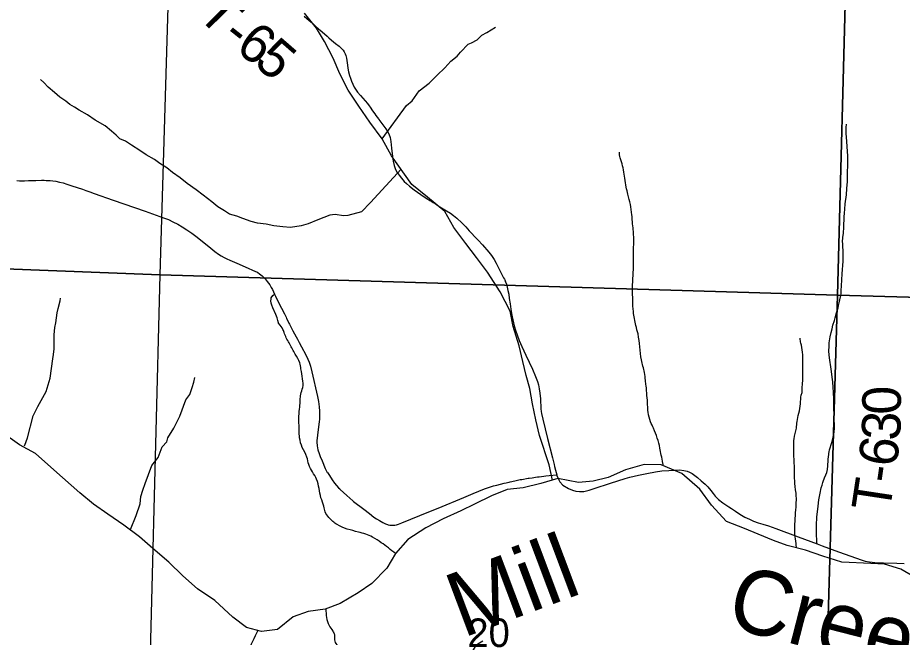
# Model space of a CAD drawing. Extents: x 6.3 to 40.3, y 9 to 31.
# Drawn here: x 9.108 to 10.406, y 26.729 to 27.639 of the extents above; entities that cross this region are included whole.
import ezdxf

# ---------------------------------------------------------------- set-up
doc = ezdxf.new("R2010")
doc.units = 0
for name, color, linetype in [('GM_X_Corporation', 7, 'Continuous'), ('GM_X_Minor_River', 7, 'Continuous'), ('GM_X_Minor_River_Text', 7, 'Continuous'), ('GM_X_Section', 7, 'Continuous'), ('GM_X_Section_Text', 7, 'Continuous'), ('GM_X_Township_Road', 7, 'Continuous'), ('GM_X_Township_Road_Text', 7, 'Continuous')]:
    doc.layers.add(name, color=color, linetype=linetype)

msp = doc.modelspace()

# ---------------------------------------------------------------- linework, layer by layer
at = {"layer": 'GM_X_Corporation'}
for points in [[(8.4446, 28.2864), (8.4446, 27.2958), (9.3175, 27.262), (9.3471, 28.2622)], [(8.4446, 27.2958), (8.4446, 26.2901), (9.2921, 26.2668), (9.3175, 27.262)]]:
    msp.add_lwpolyline(points, close=True, dxfattribs=at)
at = {"layer": 'GM_X_Minor_River'}
for points in [[(9.8928, 26.9603), (9.8883, 26.9826), (9.8739, 27.0256), (9.8686, 27.049), (9.8636, 27.0724), (9.8599, 27.0947), (9.8546, 27.114), (9.8493, 27.1347), (9.844, 27.1577), (9.8353, 27.1861), (9.8311, 27.2083), (9.8163, 27.237), (9.7978, 27.2657), (9.7815, 27.2872), (9.7656, 27.308), (9.7482, 27.3314), (9.7349, 27.3548), (9.7096, 27.3759), (9.6865, 27.3944), (9.657, 27.4367), (9.643, 27.4616), (9.6252, 27.4862), (9.6089, 27.5096), (9.5934, 27.533), (9.5809, 27.5568), (9.571, 27.5802), (9.5586, 27.6047), (9.5468, 27.624), (9.529, 27.6462)], [(9.6431, 27.4618), (9.643, 27.4616), (9.6789, 27.5103), (9.6872, 27.5172), (9.6973, 27.5321), (9.712, 27.5433), (9.724, 27.5552), (9.7349, 27.5656), (9.7439, 27.5755), (9.7533, 27.5829), (9.7578, 27.589), (9.7695, 27.6005), (9.774, 27.6025), (9.7823, 27.6071), (9.7891, 27.6136), (9.7966, 27.6175), (9.8095, 27.6256)], [(9.6709, 27.4168), (9.6257, 27.368), (9.6126, 27.3542), (9.5925, 27.3487), (9.5861, 27.3486), (9.5743, 27.3504), (9.5663, 27.3492), (9.5485, 27.3425), (9.5346, 27.3367), (9.5243, 27.3339), (9.5084, 27.3314), (9.4974, 27.3321), (9.4841, 27.3338), (9.473, 27.336), (9.4601, 27.3378), (9.4506, 27.3403), (9.4388, 27.3444), (9.4296, 27.3481), (9.419, 27.351), (9.4117, 27.3559), (9.4021, 27.3618), (9.3933, 27.3689), (9.3803, 27.3787), (9.37, 27.3865), (9.357, 27.3959), (9.3466, 27.4042), (9.3352, 27.412), (9.3271, 27.4191), (9.3168, 27.4251), (9.3088, 27.4311), (9.2969, 27.4382), (9.2873, 27.4445), (9.2751, 27.452), (9.2663, 27.458), (9.2583, 27.4617), (9.2525, 27.4669), (9.246, 27.4726), (9.2365, 27.4804), (9.2219, 27.489), (9.2108, 27.4969), (9.1986, 27.5036), (9.1914, 27.5081), (9.1849, 27.5122), (9.1791, 27.5167), (9.1699, 27.5227), (9.1623, 27.5298), (9.1527, 27.5373), (9.1465, 27.5441), (9.1419, 27.5489)], [(9.1179, 27.0109), (9.1188, 27.0117), (9.1225, 27.0223), (9.1309, 27.0547), (9.1379, 27.0685), (9.1498, 27.0902), (9.1557, 27.11), (9.1596, 27.1382), (9.161, 27.1447), (9.1617, 27.153), (9.1616, 27.1602), (9.1615, 27.1739), (9.1625, 27.1842), (9.164, 27.1914), (9.1661, 27.2059), (9.1675, 27.2123), (9.1705, 27.2234), (9.1708, 27.2276)], [(9.274, 26.888), (9.282, 26.9082), (9.2879, 26.9254), (9.289, 26.936), (9.2919, 26.9456), (9.2952, 26.9555), (9.3052, 26.9818), (9.3142, 26.9936), (9.3201, 27.0093), (9.3272, 27.0166), (9.3283, 27.0223), (9.3372, 27.0368), (9.3462, 27.0544), (9.355, 27.0784), (9.3606, 27.086), (9.3643, 27.0963), (9.3665, 27.1043), (9.3683, 27.1112)], [(9.5593, 26.7708), (9.5347, 26.7674), (9.5123, 26.7595), (9.4893, 26.741), (9.4662, 26.738), (9.4438, 26.7436), (9.4241, 26.7591), (9.3973, 26.7833), (9.3719, 26.8006), (9.3507, 26.8199), (9.3299, 26.8399), (9.3064, 26.8599), (9.2871, 26.8772), (9.264, 26.8942), (9.2405, 26.9101), (9.2193, 26.9252), (9.1996, 26.9414), (9.1614, 26.9754), (9.1345, 26.9995), (9.1111, 27.012), (9.0853, 27.0301)], [(10.4254, 26.8173), (10.4042, 26.8294), (10.38, 26.8366), (10.3603, 26.8377), (10.3176, 26.84), (10.2895, 26.8486), (10.2642, 26.8573), (10.2373, 26.8641), (10.2172, 26.8717), (10.1949, 26.8807), (10.1748, 26.8894), (10.1483, 26.8996), (10.1264, 26.9237), (10.109, 26.9471), (10.0828, 26.9698), (10.0526, 26.9826), (10.0276, 26.9834), (10.0003, 26.9754), (9.9749, 26.9641), (9.9526, 26.9588), (9.931, 26.9569), (9.9007, 26.9626), (9.8758, 26.9554), (9.85, 26.949), (9.8265, 26.9464), (9.8035, 26.9373), (9.7788, 26.9248), (9.7584, 26.915), (9.7327, 26.9033), (9.7069, 26.8901), (9.6808, 26.8731), (9.6626, 26.8527), (9.6498, 26.8312), (9.6278, 26.8086), (9.6077, 26.7946), (9.5816, 26.7791), (9.5593, 26.7708)]]:
    msp.add_lwpolyline(points, dxfattribs=at)
for points in [[(10.0554, 26.9824), (10.0551, 26.9849), (10.0527, 26.997), (10.0507, 27.0072), (10.0413, 27.0364), (10.037, 27.0458), (10.0334, 27.0599), (10.0326, 27.0709), (10.0304, 27.0986), (10.0295, 27.1069), (10.0279, 27.1183), (10.0235, 27.1368), (10.0185, 27.1751), (10.0154, 27.1873), (10.0117, 27.2077), (10.0108, 27.2237), (10.0112, 27.2609), (10.0118, 27.2712), (10.0117, 27.2825), (10.0119, 27.297), (10.0121, 27.3205), (10.0116, 27.3277), (10.0103, 27.3399), (10.0095, 27.3501), (10.0038, 27.3801), (10.0011, 27.3907), (9.999, 27.4036), (9.9942, 27.4278), (9.9923, 27.4335), (9.9914, 27.438), (9.9914, 27.4422)], [(9.6626, 26.8527), (9.6417, 26.8684), (9.6291, 26.8766), (9.6081, 26.884), (9.5769, 26.8951), (9.565, 26.9052), (9.5596, 26.9135), (9.5576, 26.9218), (9.5533, 26.9343), (9.5469, 26.9616), (9.5353, 26.9831), (9.5325, 26.9941), (9.5259, 27.0081), (9.5219, 27.0225), (9.521, 27.0437), (9.5209, 27.0543), (9.5222, 27.0676), (9.5229, 27.0779), (9.5235, 27.0863), (9.5265, 27.0962), (9.5263, 27.1091), (9.5239, 27.1235), (9.5223, 27.1326), (9.5153, 27.1454), (9.5076, 27.1598), (9.4998, 27.1753), (9.4975, 27.1817), (9.4917, 27.19)], [(10.2512, 26.8607), (10.2504, 26.8674), (10.2488, 26.8803), (10.2486, 26.8917), (10.2506, 26.9247), (10.2508, 26.9365), (10.2487, 26.9555), (10.2482, 26.971), (10.247, 27.0101), (10.2476, 27.0211), (10.2509, 27.0367), (10.2519, 27.0463), (10.2545, 27.0584), (10.257, 27.0725), (10.258, 27.085), (10.2594, 27.0904), (10.2594, 27.0965), (10.2601, 27.1025), (10.2603, 27.1177), (10.2605, 27.1303), (10.2583, 27.1584), (10.2568, 27.1648), (10.2563, 27.169)], [(9.5603, 26.7712), (9.5651, 26.7468), (9.5705, 26.7386), (9.5729, 26.7333), (9.573, 26.7257), (9.5765, 26.7185), (9.5822, 26.714), (9.5918, 26.7057), (9.601, 26.6975), (9.6079, 26.6919), (9.617, 26.6882), (9.6251, 26.6818), (9.6346, 26.6789), (9.6396, 26.6766), (9.651, 26.673), (9.6582, 26.6723), (9.6681, 26.6728), (9.6783, 26.674), (9.6897, 26.6757), (9.7034, 26.6769), (9.7079, 26.6778), (9.7166, 26.6801), (9.7242, 26.6836), (9.7329, 26.686), (9.7472, 26.693), (9.751, 26.6983), (9.7616, 26.7007), (9.7714, 26.7046), (9.7755, 26.7085), (9.7815, 26.718), (9.7909, 26.7242)], [(9.4604, 26.7394), (9.4448, 26.6757), (9.4487, 26.6647), (9.4522, 26.6553), (9.4565, 26.6439), (9.4646, 26.6357), (9.4692, 26.6327), (9.4776, 26.6221), (9.4837, 26.618), (9.493, 26.6082), (9.4979, 26.6045), (9.506, 26.5943), (9.511, 26.591), (9.5187, 26.5842), (9.5225, 26.5782), (9.5302, 26.571), (9.5409, 26.5617), (9.5474, 26.5553), (9.5494, 26.5511), (9.5571, 26.5425), (9.559, 26.5379), (9.5629, 26.533), (9.5736, 26.5218), (9.5863, 26.512), (9.5905, 26.5064), (9.5989, 26.5), (9.6066, 26.4929)]]:
    msp.add_spline(points, degree=3, dxfattribs=at)
at = {"layer": 'GM_X_Section'}
for points in [[(9.3471, 28.2622), (10.3378, 28.2352), (10.3113, 27.232), (9.3175, 27.262)], [(10.3378, 28.2352), (11.3334, 28.2025), (11.3031, 27.2038), (10.3113, 27.232)], [(9.3175, 27.262), (10.3113, 27.232), (10.2824, 26.2364), (9.2921, 26.2668)], [(10.3113, 27.232), (11.3031, 27.2038), (11.2666, 26.2073), (10.2824, 26.2364)]]:
    msp.add_lwpolyline(points, close=True, dxfattribs=at)
at = {"layer": 'GM_X_Township_Road'}
for points in [[(9.5288, 27.6416), (9.5358, 27.6354), (9.5401, 27.6319), (9.5451, 27.6272), (9.5497, 27.6231), (9.5521, 27.621), (9.5582, 27.6158), (9.5624, 27.6121), (9.5647, 27.61), (9.5689, 27.6064), (9.5746, 27.6016), (9.5799, 27.5974), (9.5831, 27.5945), (9.5856, 27.5918), (9.5874, 27.5893), (9.5888, 27.5865), (9.5898, 27.5837), (9.5906, 27.5801), (9.592, 27.5695), (9.5927, 27.5654), (9.5939, 27.56), (9.5953, 27.5547), (9.5964, 27.5506), (9.5983, 27.5464), (9.6021, 27.5376), (9.6039, 27.5344), (9.6067, 27.5303), (9.6111, 27.525), (9.6181, 27.5172), (9.6213, 27.5133), (9.6239, 27.5099), (9.6254, 27.5079), (9.6291, 27.5029), (9.6323, 27.4983), (9.634, 27.4958), (9.6357, 27.4933), (9.6376, 27.4908), (9.6382, 27.4898), (9.6484, 27.4761), (9.6507, 27.4725), (9.6528, 27.4687), (9.6547, 27.4635), (9.6559, 27.4575), (9.6568, 27.4476), (9.658, 27.4358), (9.6591, 27.4285), (9.6606, 27.4224), (9.6628, 27.4167), (9.6652, 27.4123), (9.6679, 27.4081), (9.6713, 27.4037), (9.6755, 27.3991), (9.6786, 27.396), (9.6832, 27.3919), (9.6901, 27.3866), (9.6996, 27.3796), (9.7064, 27.3752), (9.71, 27.3729), (9.7116, 27.3719), (9.7132, 27.3709), (9.7164, 27.369), (9.7179, 27.368), (9.7206, 27.3664), (9.7232, 27.3648), (9.7279, 27.3618), (9.7326, 27.3588), (9.7374, 27.3559), (9.7431, 27.3522), (9.7477, 27.349), (9.7525, 27.3451), (9.7598, 27.3383), (9.7658, 27.3321), (9.7708, 27.3266), (9.7746, 27.3225), (9.7788, 27.3179), (9.7839, 27.3125), (9.7902, 27.3057), (9.7997, 27.2951), (9.8035, 27.2901), (9.8072, 27.2844), (9.8102, 27.279), (9.8133, 27.273), (9.8152, 27.2692), (9.8177, 27.2644), (9.8213, 27.2575), (9.8224, 27.2554), (9.8229, 27.2544), (9.8234, 27.2532), (9.8238, 27.2521), (9.8245, 27.2505), (9.8253, 27.2482), (9.8267, 27.2435), (9.8272, 27.2411), (9.8277, 27.2387), (9.8287, 27.2332), (9.8296, 27.227), (9.8308, 27.2191), (9.8319, 27.2112), (9.8332, 27.2027), (9.8346, 27.1955), (9.8368, 27.1871), (9.8393, 27.1789), (9.8411, 27.1736), (9.8442, 27.1655), (9.8481, 27.1563), (9.8539, 27.144), (9.859, 27.1333), (9.8637, 27.1232), (9.8683, 27.1123), (9.8709, 27.1053), (9.8724, 27.1), (9.8736, 27.0945), (9.8746, 27.0878), (9.8753, 27.0797), (9.8759, 27.0648), (9.8764, 27.0611), (9.877, 27.0581), (9.879, 27.0496), (9.8859, 27.0213), (9.8928, 26.9929), (9.8954, 26.9833), (9.8961, 26.9803), (9.8975, 26.9749), (9.8994, 26.9682)], [(10.3188, 27.3105), (10.3191, 27.3164), (10.3199, 27.3231), (10.3204, 27.3317), (10.3211, 27.3469), (10.3213, 27.3523), (10.3218, 27.3581), (10.3226, 27.3659), (10.3243, 27.3795), (10.3251, 27.3886), (10.3258, 27.3991), (10.3259, 27.4112), (10.3262, 27.4239), (10.3262, 27.4365), (10.3255, 27.4496), (10.3249, 27.4582), (10.3242, 27.4695), (10.3238, 27.4741), (10.3241, 27.4781), (10.3243, 27.4833)], [(9.1068, 27.4001), (9.1111, 27.3997), (9.1161, 27.3997), (9.118, 27.3997), (9.1241, 27.4001), (9.1347, 27.4005), (9.1433, 27.4006), (9.1471, 27.4006), (9.1501, 27.4005), (9.1557, 27.4003), (9.1599, 27.3998), (9.1641, 27.3992), (9.1695, 27.3981), (9.1749, 27.3967), (9.1801, 27.3951), (9.1848, 27.3936), (9.1878, 27.3927), (9.1955, 27.3902), (9.2031, 27.3876), (9.2083, 27.3858), (9.2141, 27.3837), (9.2205, 27.3814), (9.2481, 27.3717), (9.2953, 27.3552), (9.3224, 27.3457), (9.3293, 27.3429), (9.3361, 27.3398), (9.3432, 27.3361), (9.3497, 27.3324), (9.3566, 27.3281), (9.3636, 27.3231), (9.3715, 27.3171), (9.3769, 27.3129), (9.3812, 27.3094), (9.3916, 27.3008), (9.3973, 27.2962), (9.4028, 27.2922), (9.4069, 27.2896), (9.4112, 27.2872), (9.4151, 27.2853), (9.4197, 27.2834), (9.43, 27.2791), (9.442, 27.2736), (9.4574, 27.2668), (9.4589, 27.2661), (9.4606, 27.2653), (9.463, 27.2635), (9.4668, 27.2602), (9.4712, 27.2559), (9.4744, 27.2521), (9.4781, 27.2471), (9.4804, 27.2434), (9.4821, 27.2401), (9.485, 27.2336)], [(10.2812, 26.8669), (10.2811, 26.869), (10.2805, 26.8828), (10.2805, 26.8942), (10.2811, 26.906), (10.2827, 26.9221), (10.2839, 26.9313), (10.2857, 26.9411), (10.2875, 26.9489), (10.2885, 26.9531), (10.2897, 26.9567), (10.2902, 26.9584), (10.2923, 26.9636), (10.2942, 26.9682), (10.2954, 26.9717), (10.2965, 26.9759), (10.2972, 26.9813), (10.2975, 26.9898), (10.2979, 26.9959), (10.2983, 26.9971), (10.2986, 27.0002), (10.2989, 27.0014), (10.2989, 27.002), (10.2997, 27.005), (10.3031, 27.0156), (10.3046, 27.021), (10.3056, 27.0259), (10.3063, 27.0308), (10.3066, 27.0364), (10.3066, 27.042), (10.3062, 27.0482), (10.3062, 27.0575), (10.3061, 27.0649), (10.3057, 27.0791), (10.3052, 27.0897), (10.3048, 27.0965), (10.3042, 27.1045), (10.3034, 27.1113), (10.3024, 27.1199), (10.3016, 27.1265), (10.3, 27.1367), (10.2991, 27.1439), (10.2987, 27.1504), (10.2988, 27.1565), (10.2992, 27.1619), (10.3006, 27.1709), (10.3019, 27.1769), (10.3032, 27.1823), (10.3046, 27.1877), (10.3067, 27.1948), (10.3078, 27.1984), (10.3083, 27.2002), (10.309, 27.2025), (10.31, 27.2061), (10.312, 27.2133), (10.3129, 27.2169), (10.3137, 27.2205), (10.3148, 27.2253), (10.3159, 27.2313), (10.3164, 27.2343), (10.3168, 27.2386), (10.3172, 27.2454), (10.3183, 27.2633), (10.3194, 27.2818), (10.3197, 27.2874), (10.3196, 27.2949), (10.3193, 27.3054), (10.319, 27.3079), (10.3188, 27.3105)], [(9.4912, 27.1894), (9.4901, 27.1949), (9.489, 27.1985), (9.487, 27.2037), (9.4827, 27.2134), (9.481, 27.2174), (9.4802, 27.2204), (9.4798, 27.2235), (9.48, 27.226), (9.4804, 27.2278), (9.4827, 27.2313), (9.485, 27.2336)], [(9.485, 27.2336), (9.4866, 27.2303), (9.4902, 27.2232), (9.4955, 27.2128), (9.4995, 27.2044), (9.5021, 27.1995), (9.5028, 27.1979), (9.505, 27.1934), (9.5063, 27.1908), (9.5071, 27.1891), (9.5122, 27.1794), (9.5169, 27.1705), (9.5187, 27.1673), (9.5214, 27.1625), (9.5249, 27.1561), (9.531, 27.1445), (9.5342, 27.1377), (9.5358, 27.1337), (9.5377, 27.1278), (9.5399, 27.1194), (9.5481, 27.0832), (9.5496, 27.0759), (9.5507, 27.0679), (9.5511, 27.0617), (9.5512, 27.0568), (9.5509, 27.05), (9.5505, 27.0457), (9.5487, 27.0307), (9.5482, 27.0264), (9.5474, 27.018), (9.5473, 27.0159), (9.5476, 27.0108), (9.5481, 27.0076), (9.5488, 27.0047), (9.5506, 26.9993), (9.5522, 26.9949), (9.5549, 26.9885), (9.5594, 26.9774), (9.5616, 26.9732), (9.5625, 26.9717), (9.5631, 26.9708), (9.5695, 26.9608), (9.5729, 26.956), (9.5789, 26.9489), (9.5807, 26.9474), (9.5816, 26.9465), (9.5911, 26.9379), (9.6, 26.9299), (9.6009, 26.9291), (9.6161, 26.9174), (9.6243, 26.9111), (9.6306, 26.9061), (9.6348, 26.9034), (9.639, 26.9008), (9.6439, 26.8981), (9.6479, 26.8962), (9.6507, 26.8953), (9.652, 26.8948), (9.6544, 26.8942), (9.6581, 26.8939), (9.6618, 26.8941), (9.6642, 26.8947), (9.6672, 26.8956), (9.6717, 26.8975), (9.7116, 26.9136), (9.7254, 26.9192), (9.7629, 26.9346), (9.7767, 26.9404), (9.7931, 26.9473), (9.8034, 26.9511), (9.8064, 26.9518), (9.8112, 26.9531), (9.822, 26.9558), (9.825, 26.9565), (9.8268, 26.9569), (9.8292, 26.9575), (9.831, 26.958), (9.8334, 26.9585), (9.8352, 26.9589), (9.8377, 26.9594), (9.8395, 26.9598), (9.8455, 26.961), (9.8479, 26.9614), (9.8571, 26.963), (9.8589, 26.9633), (9.8632, 26.9638), (9.868, 26.9644), (9.871, 26.9651), (9.8735, 26.9653), (9.8802, 26.966), (9.8832, 26.9664), (9.8879, 26.9669), (9.8994, 26.9682)], [(9.8994, 26.9682), (9.8996, 26.9671), (9.9008, 26.9638), (9.9038, 26.9579), (9.9083, 26.953), (9.9166, 26.9481), (9.9224, 26.9454), (9.9275, 26.944), (9.9326, 26.9435), (9.939, 26.9435), (9.9467, 26.9454), (9.954, 26.9479), (9.9779, 26.9557), (9.9995, 26.9628), (10.0066, 26.9647), (10.0193, 26.9676), (10.0315, 26.9702), (10.0443, 26.9725), (10.0536, 26.9737), (10.0635, 26.9745), (10.0709, 26.9748), (10.0747, 26.975), (10.0796, 26.9752), (10.0858, 26.9746), (10.0906, 26.9733), (10.094, 26.9719), (10.0978, 26.9698), (10.102, 26.9671), (10.1059, 26.964), (10.1114, 26.959), (10.1171, 26.9542), (10.121, 26.9502), (10.1252, 26.9449), (10.1286, 26.9404), (10.1317, 26.9365), (10.1366, 26.9318), (10.143, 26.9269), (10.1519, 26.9211), (10.1555, 26.9188), (10.1616, 26.9145), (10.1678, 26.9104), (10.1753, 26.906), (10.182, 26.9027), (10.1882, 26.8999), (10.1946, 26.8976), (10.2018, 26.8955), (10.2098, 26.893), (10.2209, 26.8892), (10.2534, 26.8772), (10.2812, 26.8669)], [(10.2812, 26.8669), (10.2889, 26.864), (10.3128, 26.8551), (10.3227, 26.8514), (10.346, 26.843), (10.352, 26.8413), (10.3581, 26.8402), (10.3661, 26.8394), (10.3786, 26.8389), (10.3984, 26.8385), (10.409, 26.8379)]]:
    msp.add_lwpolyline(points, dxfattribs=at)

# ---------------------------------------------------------------- texts
at = {"layer": 'GM_X_Minor_River_Text'}
for s, rotation, p in [('Mill', 20.6147, (9.7612, 26.7281)), ('Creek', 345.6151, (10.1452, 26.7456))]:
    msp.add_text(s, height=0.0947, rotation=rotation, dxfattribs=at).set_placement(p)
at = {"layer": 'GM_X_Section_Text'}
msp.add_text('20', height=0.04186, rotation=0, dxfattribs=at).set_placement((9.7681, 26.7152))
at = {"layer": 'GM_X_Township_Road_Text'}
for s, rotation, p in [('T', 314.9061, (9.3702, 27.6424)), ('-', 321.6692, (9.4056, 27.6074)), ('6', 323.8193, (9.4258, 27.5915)), ('5', 318.9737, (9.453, 27.5717)), ('0', 90.9294, (10.4047, 27.057)), ('3', 86.7335, (10.4026, 27.0175)), ('6', 82.5175, (10.3976, 26.9783)), ('-', 81.6014, (10.3941, 26.9542)), ('T', 81.3793, (10.3877, 26.912))]:
    msp.add_text(s, height=0.0568, rotation=rotation, dxfattribs=at).set_placement(p)

doc.saveas('drawing.dxf')
